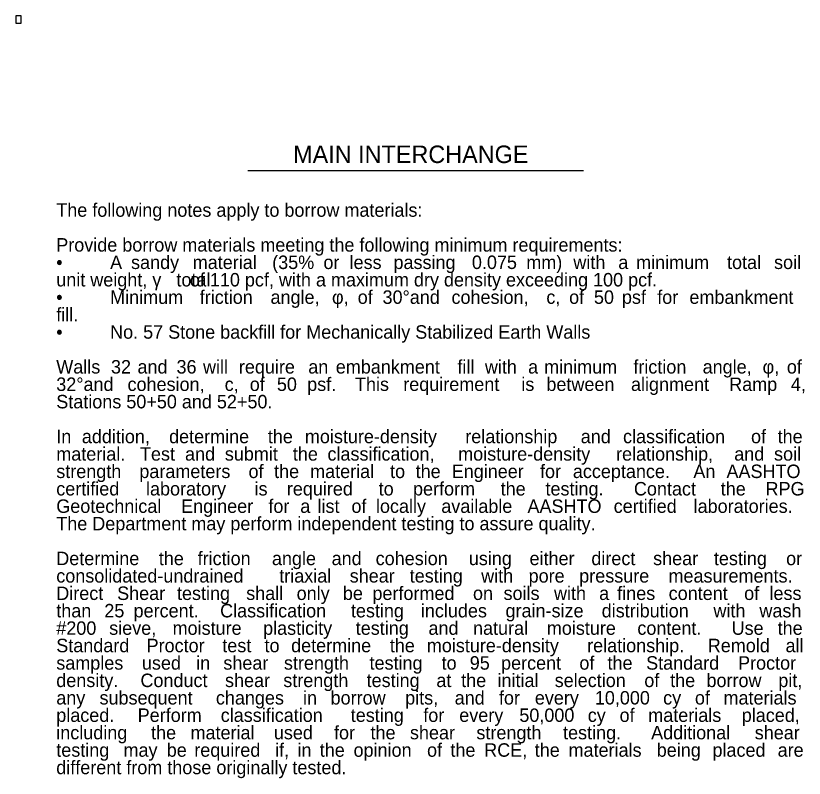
# Model space of a CAD drawing. Extents: x 4804 to 5434, y 4929 to 5221.
# Drawn here: x 5013.6 to 5094.7, y 5142.6 to 5221 of the extents above; entities that cross this region are included whole.
import ezdxf

# ---------------------------------------------------------------- set-up
doc = ezdxf.new("R2010")
doc.units = 0
doc.layers.add('RD_TX_RoadID', color=7, linetype='Continuous')

msp = doc.modelspace()

# ---------------------------------------------------------------- linework, layer by layer
at = {"layer": 'RD_TX_RoadID'}
msp.add_line((5037.503, 5205.101), (5072.019, 5205.101), dxfattribs=at)
msp.add_lwpolyline([(5013.637, 5220.248), (5014.196, 5220.248), (5014.196, 5221.019), (5013.637, 5221.019)], close=True, dxfattribs=at)

# ---------------------------------------------------------------- texts
for s, height, p in [('MAIN INTERCHANGE', 1.8, (5042.165, 5205.869)), ('The following notes apply to borrow materials:', 1.3845, (5017.804, 5200.343)), ('Provide borrow materials meeting the following minimum requirements:', 1.3845, (5017.804, 5196.759)), ('A ', 1.3845, (5023.342, 5194.967)), ('sandy ', 1.3845, (5025.495, 5194.967)), ('material ', 1.3845, (5031.84, 5194.967)), ('(35% ', 1.3845, (5040.012, 5194.967)), ('less ', 1.3845, (5047.972, 5194.967)), ('passing ', 1.3845, (5052.49, 5194.967)), ('0.075 ', 1.3845, (5060.554, 5194.967)), ('mm) ', 1.3845, (5066.148, 5194.967)), ('with ', 1.3845, (5070.988, 5194.967)), ('minimum ', 1.3845, (5077.442, 5194.967)), ('total ', 1.3845, (5086.796, 5194.967)), ('soil ', 1.3845, (5091.633, 5194.967)), ('•', 1.384, (5017.804, 5194.967)), ('or ', 1.3845, (5045.282, 5194.967)), ('a ', 1.3845, (5075.611, 5194.967)), ('unit weight, γ', 1.3845, (5017.804, 5193.175)), ('total ', 1.3845, (5030.16, 5193.175)), ('of 110 pcf, with a maximum dry density exceeding 100 pcf. ', 1.3845, (5031.545, 5193.175)), ('Minimum ', 1.3845, (5023.342, 5191.384)), ('friction ', 1.3845, (5032.56, 5191.384)), ('angle, ', 1.3845, (5039.842, 5191.384)), ('of ', 1.3845, (5048.809, 5191.384)), ('30°and ', 1.3845, (5051.364, 5191.384)), ('cohesion, ', 1.3845, (5058.456, 5191.384)), ('of ', 1.3845, (5070.554, 5191.384)), ('psf ', 1.3845, (5075.988, 5191.384)), ('for ', 1.3845, (5079.618, 5191.384)), ('embankment ', 1.3845, (5082.925, 5191.384)), ('•', 1.384, (5017.804, 5191.384)), ('φ, ', 1.3845, (5046.16, 5191.384)), ('c, ', 1.3845, (5068.213, 5191.384)), ('50 ', 1.3845, (5073.109, 5191.384)), ('fill.', 1.3845, (5017.804, 5189.592)), ('No. 57 Stone backfill for Mechanically Stabilized Earth Walls', 1.3845, (5023.342, 5187.8)), ('•', 1.384, (5017.804, 5187.8)), ('Walls ', 1.3845, (5017.804, 5184.216)), ('32 ', 1.3845, (5023.43, 5184.216)), ('and ', 1.3845, (5026.156, 5184.216)), ('36 ', 1.3845, (5030.171, 5184.216)), ('will ', 1.3845, (5032.897, 5184.216)), ('require ', 1.3845, (5036.589, 5184.216)), ('embankment ', 1.3845, (5046.554, 5184.216)), ('fill ', 1.3845, (5059.06, 5184.216)), ('with ', 1.3845, (5061.891, 5184.216)), ('minimum ', 1.3845, (5067.985, 5184.216)), ('friction ', 1.3845, (5077.159, 5184.216)), ('angle, ', 1.3845, (5084.288, 5184.216)), ('of ', 1.3845, (5092.949, 5184.216)), ('an ', 1.3845, (5043.721, 5184.216)), ('a ', 1.3845, (5066.334, 5184.216)), ('φ, ', 1.3845, (5090.452, 5184.216)), ('32°and ', 1.3845, (5017.804, 5182.424)), ('cohesion, ', 1.3845, (5025.133, 5182.424)), ('c, ', 1.3845, (5035.126, 5182.424)), ('of ', 1.3845, (5037.704, 5182.424)), ('50 ', 1.3845, (5040.495, 5182.424)), ('psf. ', 1.3845, (5043.612, 5182.424)), (' This ', 1.3845, (5048.015, 5182.424)), ('requirement ', 1.3845, (5053.494, 5182.424)), ('is ', 1.3845, (5065.637, 5182.424)), ('between ', 1.3845, (5068.215, 5182.424)), ('alignment ', 1.3845, (5076.919, 5182.424)), ('Ramp ', 1.3845, (5087.019, 5182.424)), ('4, ', 1.3845, (5093.359, 5182.424)), ('Stations 50+50 and 52+50.', 1.3845, (5017.804, 5180.633)), ('In ', 1.3845, (5017.804, 5177.049)), ('addition, ', 1.3845, (5020.436, 5177.049)), ('determine ', 1.3845, (5029.407, 5177.049)), ('the ', 1.3845, (5039.564, 5177.049)), ('moisture-density ', 1.3845, (5043.378, 5177.049)), ('relationship ', 1.3845, (5059.873, 5177.049)), ('and ', 1.3845, (5071.747, 5177.049)), ('classification ', 1.3845, (5076.1, 5177.049)), ('of ', 1.3845, (5089.264, 5177.049)), ('the ', 1.3845, (5092.003, 5177.049)), ('material. ', 1.3845, (5017.804, 5175.257)), ('Test ', 1.3845, (5026.414, 5175.257)), ('and ', 1.3845, (5031.047, 5175.257)), ('submit ', 1.3845, (5035.143, 5175.257)), ('the ', 1.3845, (5042.14, 5175.257)), ('classification, ', 1.3845, (5045.698, 5175.257)), ('moisture-density ', 1.3845, (5059.143, 5175.257)), ('relationship, ', 1.3845, (5075.382, 5175.257)), ('and ', 1.3845, (5087.537, 5175.257)), ('soil ', 1.3845, (5091.633, 5175.257)), ('strength ', 1.3845, (5017.804, 5173.465)), ('parameters ', 1.3845, (5026.346, 5173.465)), ('of ', 1.3845, (5037.578, 5173.465)), ('the ', 1.3845, (5040.209, 5173.465)), ('material ', 1.3845, (5043.916, 5173.465)), ('to ', 1.3845, (5052.138, 5173.465)), ('the ', 1.3845, (5054.769, 5173.465)), ('Engineer ', 1.3845, (5058.476, 5173.465)), ('for ', 1.3845, (5067.558, 5173.465)), ('acceptance. ', 1.3845, (5070.941, 5173.465)), (' An ', 1.3845, (5082.819, 5173.465)), ('AASHTO ', 1.3845, (5086.741, 5173.465)), ('certified ', 1.3845, (5017.804, 5171.673)), ('laboratory ', 1.3845, (5027.033, 5171.673)), ('is ', 1.3845, (5038.198, 5171.673)), ('required ', 1.3845, (5041.518, 5171.673)), ('to ', 1.3845, (5050.964, 5171.673)), ('perform ', 1.3845, (5054.497, 5171.673)), ('the ', 1.3845, (5063.513, 5171.673)), ('testing. ', 1.3845, (5068.121, 5171.673)), (' Contact ', 1.3845, (5076.705, 5171.673)), ('the ', 1.3845, (5086.148, 5171.673)), ('RPG ', 1.3845, (5090.757, 5171.673)), ('Geotechnical ', 1.3845, (5017.804, 5169.882)), ('Engineer ', 1.3845, (5030.647, 5169.882)), ('for ', 1.3845, (5039.621, 5169.882)), ('a ', 1.3845, (5042.898, 5169.882)), ('list ', 1.3845, (5044.671, 5169.882)), ('of ', 1.3845, (5048.163, 5169.882)), ('locally ', 1.3845, (5050.686, 5169.882)), ('available ', 1.3845, (5057.404, 5169.882)), ('AASHTO ', 1.3845, (5066.272, 5169.882)), ('certified ', 1.3845, (5075.138, 5169.882)), ('laboratories. ', 1.3845, (5083.359, 5169.882)), ('The Department may perform independent testing to assure quality. ', 1.3845, (5017.804, 5168.09)), ('Determine ', 1.3845, (5017.804, 5164.506)), ('the ', 1.3845, (5028.352, 5164.506)), ('friction ', 1.3845, (5032.343, 5164.506)), ('angle ', 1.3845, (5039.986, 5164.506)), ('and ', 1.3845, (5046.127, 5164.506)), ('cohesion ', 1.3845, (5050.656, 5164.506)), ('using ', 1.3845, (5060.236, 5164.506)), ('either ', 1.3845, (5066.484, 5164.506)), ('direct ', 1.3845, (5072.84, 5164.506)), ('shear ', 1.3845, (5079.195, 5164.506)), ('testing ', 1.3845, (5085.445, 5164.506)), ('or ', 1.3845, (5092.874, 5164.506)), ('consolidated-undrained ', 1.3845, (5017.804, 5162.714)), ('triaxial ', 1.3845, (5040.738, 5162.714)), ('shear ', 1.3845, (5047.985, 5162.714)), ('testing ', 1.3845, (5054.158, 5162.714)), ('with ', 1.3845, (5061.509, 5162.714)), ('pore ', 1.3845, (5066.389, 5162.714)), ('pressure ', 1.3845, (5071.594, 5162.714)), ('measurements. ', 1.3845, (5080.776, 5162.714)), ('Direct ', 1.3845, (5017.804, 5160.922)), ('Shear ', 1.3845, (5024.065, 5160.922)), ('testing ', 1.3845, (5030.221, 5160.922)), ('shall ', 1.3845, (5037.34, 5160.922)), ('only ', 1.3845, (5042.527, 5160.922)), ('be ', 1.3845, (5047.283, 5160.922)), ('performed ', 1.3845, (5050.321, 5160.922)), ('on ', 1.3845, (5060.666, 5160.922)), ('soils ', 1.3845, (5063.81, 5160.922)), ('with ', 1.3845, (5068.997, 5160.922)), ('a ', 1.3845, (5073.644, 5160.922)), ('fines ', 1.3845, (5075.5, 5160.922)), ('content ', 1.3845, (5080.794, 5160.922)), ('of ', 1.3845, (5088.557, 5160.922)), ('less ', 1.3845, (5091.163, 5160.922)), ('than ', 1.3845, (5017.804, 5159.131)), ('25 ', 1.3845, (5022.747, 5159.131)), ('percent. ', 1.3845, (5025.757, 5159.131)), (' Classification ', 1.3845, (5034.14, 5159.131)), ('testing ', 1.3845, (5048.11, 5159.131)), ('includes ', 1.3845, (5055.309, 5159.131)), ('grain-size ', 1.3845, (5064.015, 5159.131)), ('distribution ', 1.3845, (5073.903, 5159.131)), ('with ', 1.3845, (5085.398, 5159.131)), ('wash ', 1.3845, (5090.126, 5159.131)), ('sieve, ', 1.3845, (5023.249, 5157.339)), ('moisture ', 1.3845, (5029.768, 5157.339)), ('plasticity ', 1.3845, (5039.079, 5157.339)), ('testing ', 1.3845, (5048.605, 5157.339)), ('and ', 1.3845, (5056.088, 5157.339)), ('natural ', 1.3845, (5060.67, 5157.339)), ('moisture ', 1.3845, (5068.262, 5157.339)), ('the ', 1.3845, (5092.003, 5157.339)), ('#200 ', 1.3845, (5017.804, 5157.339)), ('content. ', 1.3845, (5077.573, 5157.339)), ('  Use ', 1.3845, (5086.237, 5157.339)), ('Standard ', 1.3845, (5017.804, 5155.547)), ('Proctor ', 1.3845, (5027.094, 5155.547)), ('test ', 1.3845, (5034.88, 5155.547)), ('to ', 1.3845, (5039.226, 5155.547)), ('determine ', 1.3845, (5041.959, 5155.547)), ('the ', 1.3845, (5052.11, 5155.547)), ('moisture-density ', 1.3845, (5055.918, 5155.547)), ('relationship. ', 1.3845, (5072.408, 5155.547)), ('Remold ', 1.3845, (5084.814, 5155.547)), ('all ', 1.3845, (5092.815, 5155.547)), ('samples ', 1.3845, (5017.804, 5153.755)), ('used ', 1.3845, (5026.615, 5153.755)), ('in ', 1.3845, (5032.199, 5153.755)), ('shear ', 1.3845, (5034.989, 5153.755)), ('strength ', 1.3845, (5041.22, 5153.755)), ('testing ', 1.3845, (5050.026, 5153.755)), ('to ', 1.3845, (5057.436, 5153.755)), ('95 ', 1.3845, (5060.332, 5153.755)), ('percent ', 1.3845, (5063.553, 5153.755)), ('of ', 1.3845, (5071.609, 5153.755)), ('the ', 1.3845, (5074.505, 5153.755)), ('Standard ', 1.3845, (5078.476, 5153.755)), ('Proctor ', 1.3845, (5087.93, 5153.755)), ('density. ', 1.3845, (5017.804, 5151.963)), (' Conduct ', 1.3845, (5025.946, 5151.963)), ('shear ', 1.3845, (5035.161, 5151.963)), ('strength ', 1.3845, (5041.155, 5151.963)), ('testing ', 1.3845, (5049.725, 5151.963)), ('at ', 1.3845, (5056.898, 5151.963)), ('the ', 1.3845, (5059.452, 5151.963)), ('initial ', 1.3845, (5063.187, 5151.963)), ('selection ', 1.3845, (5069.07, 5151.963)), ('of ', 1.3845, (5078.287, 5151.963)), ('the ', 1.3845, (5080.947, 5151.963)), ('borrow ', 1.3845, (5084.682, 5151.963)), ('pit, ', 1.3845, (5092.072, 5151.963)), ('subsequent ', 1.3845, (5022.252, 5150.171)), ('changes ', 1.3845, (5034.222, 5150.171)), ('in ', 1.3845, (5043.184, 5150.171)), ('borrow ', 1.3845, (5046.019, 5150.171)), ('pits, ', 1.3845, (5053.69, 5150.171)), ('and ', 1.3845, (5058.781, 5150.171)), ('for ', 1.3845, (5063.335, 5150.171)), ('10,000 ', 1.3845, (5073.198, 5150.171)), ('of ', 1.3845, (5083.493, 5150.171)), ('materials ', 1.3845, (5086.435, 5150.171)), ('any ', 1.3845, (5017.804, 5150.171)), ('every ', 1.3845, (5067.029, 5150.171)), ('cy ', 1.3845, (5080.227, 5150.171)), ('placed. ', 1.3845, (5017.804, 5148.38)), ('Perform ', 1.3845, (5026.177, 5148.38)), ('classification ', 1.3845, (5034.717, 5148.38)), ('testing ', 1.3845, (5048.092, 5148.38)), ('for ', 1.3845, (5055.554, 5148.38)), ('of ', 1.3845, (5075.744, 5148.38)), ('materials ', 1.3845, (5078.693, 5148.38)), ('placed, ', 1.3845, (5088.308, 5148.38)), ('every ', 1.3845, (5059.256, 5148.38)), ('50,000 ', 1.3845, (5065.433, 5148.38)), ('cy ', 1.3845, (5072.47, 5148.38)), ('including ', 1.3845, (5017.804, 5146.588)), ('the ', 1.3845, (5027.556, 5146.588)), ('material ', 1.3845, (5031.613, 5146.588)), ('used ', 1.3845, (5040.186, 5146.588)), (' for ', 1.3845, (5045.856, 5146.588)), ('the ', 1.3845, (5050.127, 5146.588)), ('shear ', 1.3845, (5054.184, 5146.588)), (' strength ', 1.3845, (5060.501, 5146.588)), ('testing. ', 1.3845, (5069.93, 5146.588)), ('  Additional ', 1.3845, (5077.962, 5146.588)), ('shear ', 1.3845, (5089.648, 5146.588)), ('testing ', 1.3845, (5017.804, 5144.796)), ('may ', 1.3845, (5024.719, 5144.796)), ('be ', 1.3845, (5029.166, 5144.796)), ('required ', 1.3845, (5032, 5144.796)), ('if, ', 1.3845, (5040.314, 5144.796)), ('in ', 1.3845, (5042.608, 5144.796)), ('the ', 1.3845, (5044.904, 5144.796)), ('opinion ', 1.3845, (5048.381, 5144.796)), ('of ', 1.3845, (5055.941, 5144.796)), ('the ', 1.3845, (5058.343, 5144.796)), ('RCE, ', 1.3845, (5061.82, 5144.796)), ('the ', 1.3845, (5067.018, 5144.796)), ('materials ', 1.3845, (5070.496, 5144.796)), ('being ', 1.3845, (5079.564, 5144.796)), ('placed ', 1.3845, (5085.298, 5144.796)), ('are ', 1.3845, (5092.001, 5144.796)), ('different from those originally tested. ', 1.3845, (5017.804, 5143.004))]:
    msp.add_text(s, height=height, dxfattribs=at).set_placement(p)

doc.saveas('drawing.dxf')
